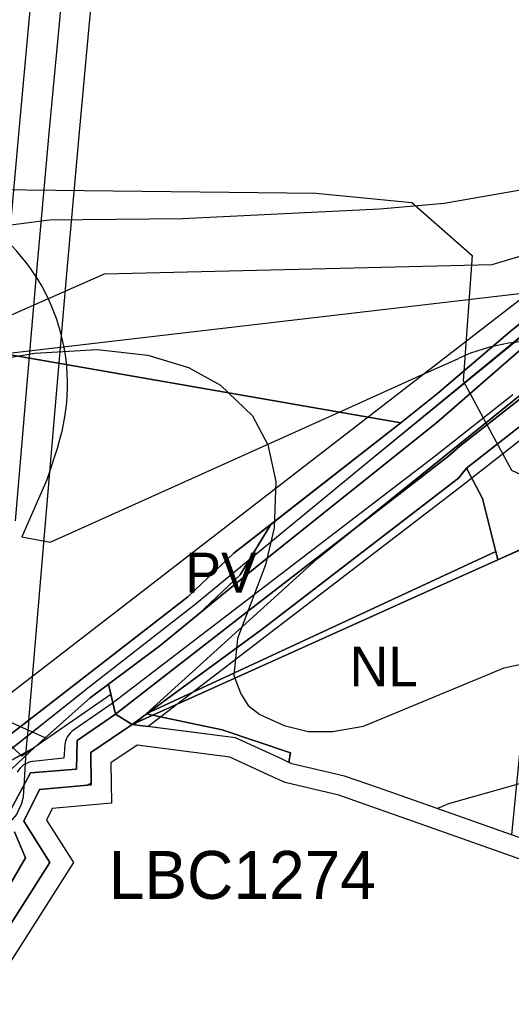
# Model space of a CAD drawing. Extents: x -758499 to -754160, y -1175205 to -1172032.
# Drawn here: x -756598.2 to -756475, y -1174594.7 to -1174350.7 of the extents above; entities that cross this region are included whole.
import ezdxf

# ---------------------------------------------------------------- set-up
doc = ezdxf.new("R2010")
doc.units = 0
for name, color, linetype in [('A040_Les50_p', 7, 'Continuous'), ('A041_BPEJ_p', 7, 'Continuous'), ('A043_InvPuda_p', 7, 'Continuous'), ('A050_Q100_p', 7, 'Continuous'), ('A053_ZvlPovoden_p', 7, 'Continuous'), ('A068_Vodovod_l', 7, 'Continuous'), ('A082_RSS_l', 7, 'Continuous'), ('A106_CykloT_l', 7, 'Continuous'), ('A106_TuristT_l', 7, 'Continuous'), ('HRANICE změn v krajině', 7, 'Continuous'), ('HRANICE řešeného území', 7, 'Continuous'), ('indexy RZV_TYP_1', 7, 'Continuous'), ('LIMITY OP vodovodu', 7, 'Continuous'), ('NÁVRH NL lesní', 7, 'Continuous'), ('PLOCHY NL lesní', 7, 'Continuous'), ('PLOCHY NS smíšené nezastavěného území', 7, 'Continuous'), ('PLOCHY NZo zemědělské-orná půda', 7, 'Continuous'), ('PLOCHY NZt zeměděl-trvalý travní porost', 7, 'Continuous'), ('PLOCHY PV prostranství veřejné', 7, 'Continuous'), ('PLOCHY VV vodní a vodohospodářské', 7, 'Continuous'), ('protipovodňová opatření- obnova ramene NÁVRH', 7, 'Continuous'), ('VPO RO retenční opatření - plochy', 7, 'Continuous'), ('vrstevnice', 7, 'Continuous'), ('ZPF obrys ploch k odnětí', 7, 'Continuous'), ('ZPF třída ochrany III', 7, 'Continuous'), ('ÚSES LBC jako součást RBK', 7, 'Continuous'), ('ÚSES LBK funkční', 7, 'Continuous'), ('ÚSES NBK funkční', 7, 'Continuous')]:
    doc.layers.add(name, color=color, linetype=linetype)

msp = doc.modelspace()

# ---------------------------------------------------------------- linework, layer by layer
at = {"layer": 'A040_Les50_p'}
for p, q in [((-756498.95, -1174440.27), (-756488.31, -1174435.48)), ((-756515.76, -1174447.84), (-756498.95, -1174440.27))]:
    msp.add_line(p, q, dxfattribs=at)
for points in [[(-756590.49, -1174481.49), (-756585.1, -1174479.07), (-756515.76, -1174447.84)], [(-756588.52, -1174457.25), (-756591.29, -1174465.89), (-756597.6, -1174480.1), (-756590.49, -1174481.49)]]:
    msp.add_lwpolyline(points, dxfattribs=at)
for centre, start, end in [((-756636.13, -1174441.98), 342.2144, 114.2004), ((-756467.78, -1174481.07), 354.3867, 114.2367), ((-756478.42, -1174485.86), 114.2367, 114.2433), ((-756495.23, -1174493.43), 114.2433, 114.247)]:
    msp.add_arc(centre, 50, start, end, dxfattribs=at)
at = {"layer": 'A041_BPEJ_p'}
for p, q in [((-756437.63, -1174416.24), (-756515.58, -1174479.13)), ((-756515.58, -1174479.13), (-756437.63, -1174416.24)), ((-756475.43, -1174428.83), (-756458.44, -1174415.07)), ((-756458.44, -1174415.07), (-756475.43, -1174428.83)), ((-756493.49, -1174444.31), (-756475.43, -1174428.83)), ((-756475.43, -1174428.83), (-756493.49, -1174444.31)), ((-756471.9, -1174432.58), (-756493.78, -1174451.61)), ((-756493.78, -1174451.61), (-756471.9, -1174432.58)), ((-756502.69, -1174451.65), (-756493.49, -1174444.31)), ((-756493.49, -1174444.31), (-756502.69, -1174451.65)), ((-756493.78, -1174451.61), (-756538.25, -1174487.18)), ((-756538.25, -1174487.18), (-756493.78, -1174451.61)), ((-756535.23, -1174477.02), (-756502.69, -1174451.65)), ((-756502.69, -1174451.65), (-756535.23, -1174477.02)), ((-756542.94, -1174489.61), (-756535.23, -1174477.02)), ((-756535.23, -1174477.02), (-756542.94, -1174489.61)), ((-756515.58, -1174479.13), (-756541.52, -1174499.18)), ((-756523.67, -1174485.65), (-756515.58, -1174479.13)), ((-756467.78, -1174481.07), (-756478.42, -1174485.86)), ((-756478.42, -1174485.86), (-756467.78, -1174481.07)), ((-756478.94, -1174483.82), (-756566.43, -1174524.45)), ((-756566.43, -1174524.45), (-756478.94, -1174483.82)), ((-756478.42, -1174485.86), (-756478.94, -1174483.82)), ((-756478.94, -1174483.82), (-756478.42, -1174485.86)), ((-756566.43, -1174524.45), (-756523.67, -1174485.65)), ((-756538.25, -1174487.18), (-756553.39, -1174499.51)), ((-756553.39, -1174499.51), (-756538.25, -1174487.18)), ((-756553.39, -1174499.51), (-756542.94, -1174489.61)), ((-756542.94, -1174489.61), (-756553.39, -1174499.51)), ((-756541.52, -1174499.18), (-756569.68, -1174521.07)), ((-756575.27, -1174519.59), (-756597.58, -1174535.01)), ((-756574.1, -1174524.5), (-756575.27, -1174519.59)), ((-756569.68, -1174521.07), (-756574.1, -1174524.5)), ((-756569.49, -1174527.16), (-756566.43, -1174524.45)), ((-756547.43, -1174528.41), (-756566.43, -1174524.45)), ((-756566.43, -1174524.45), (-756547.43, -1174528.41)), ((-756530.34, -1174534.21), (-756547.43, -1174528.41)), ((-756547.43, -1174528.41), (-756530.34, -1174534.21)), ((-756597.58, -1174535.01), (-756602.01, -1174530.76)), ((-756530.73, -1174536.56), (-756530.34, -1174534.21)), ((-756530.34, -1174534.21), (-756530.73, -1174536.56)), ((-756581.6, -1174542.33), (-756580.21, -1174541.74))]:
    msp.add_line(p, q, dxfattribs=at)
for points in [[(-756530.73, -1174536.56), (-756531.23, -1174536.33), (-756532.74, -1174535.64), (-756544.1, -1174530.4), (-756569.49, -1174527.16)], [(-756475, -1174554.72), (-756497.9, -1174546.65), (-756508.56, -1174542.9), (-756516.8, -1174540), (-756530, -1174536.9), (-756530.73, -1174536.56)], [(-756580.21, -1174541.74), (-756580.2, -1174542.2), (-756581.6, -1174542.33)]]:
    msp.add_lwpolyline(points, dxfattribs=at)
at = {"layer": 'A043_InvPuda_p'}
msp.add_line((-756366.82, -1174338.86), (-756610.15, -1174526.83), dxfattribs=at)
at = {"layer": 'A050_Q100_p'}
for p, q in [((-756640.05, -1174392.82), (-756523.95, -1174394.14)), ((-756523.95, -1174394.14), (-756499.99, -1174396.5)), ((-756499.99, -1174396.5), (-756484.85, -1174409.74)), ((-756484.85, -1174409.74), (-756487.12, -1174441.13)), ((-756487.12, -1174441.13), (-756475.01, -1174463.45)), ((-756475.01, -1174463.45), (-756453.44, -1174473.66))]:
    msp.add_line(p, q, dxfattribs=at)
at = {"layer": 'A053_ZvlPovoden_p'}
msp.add_lwpolyline([(-756442.75, -1174566.23), (-756447.2, -1174564.5), (-756475, -1174554.72), (-756497.9, -1174546.65), (-756508.56, -1174542.9), (-756516.8, -1174540), (-756530, -1174536.9), (-756531.23, -1174536.33), (-756532.74, -1174535.64), (-756544.1, -1174530.4), (-756570, -1174527.1), (-756580.3, -1174534.1), (-756580.2, -1174542.2), (-756593.2, -1174543.4), (-756597.1, -1174551.3), (-756590.6, -1174561.6), (-756610.6, -1174593)], dxfattribs=at)
at = {"layer": 'A068_Vodovod_l'}
for p, q in [((-756585.96, -1174328.29), (-756588.26, -1174351.74)), ((-756588.26, -1174351.74), (-756590.71, -1174378.21)), ((-756590.71, -1174378.21), (-756593.98, -1174414.56)), ((-756593.98, -1174414.56), (-756596.79, -1174447.61)), ((-756596.79, -1174447.61), (-756599.23, -1174476.12))]:
    msp.add_line(p, q, dxfattribs=at)
at = {"layer": 'A082_RSS_l'}
msp.add_line((-755336.54, -1174286.94), (-757157.2, -1174499.04), dxfattribs=at)
at = {"layer": 'A106_CykloT_l'}
for p, q in [((-756454.78, -1174415.63), (-756510.66, -1174461.22)), ((-756510.66, -1174461.22), (-756554.2, -1174497.04)), ((-756554.2, -1174497.04), (-756580.75, -1174517.73))]:
    msp.add_line(p, q, dxfattribs=at)
msp.add_lwpolyline([(-756580.75, -1174517.73), (-756603.81, -1174536.06), (-756634.48, -1174569.59), (-756661.16, -1174595.4)], dxfattribs=at)
at = {"layer": 'A106_TuristT_l'}
for p, q in [((-756428.85, -1174393.94), (-756510.66, -1174461.22)), ((-756510.66, -1174461.22), (-756554.2, -1174497.04)), ((-756554.2, -1174497.04), (-756580.75, -1174517.73)), ((-756580.75, -1174517.73), (-756603.81, -1174536.06))]:
    msp.add_line(p, q, dxfattribs=at)
msp.add_lwpolyline([(-756901.81, -1174477.78), (-756825.76, -1174458.08), (-756805.07, -1174450.48), (-756774.77, -1174444.62), (-756739.5, -1174452.1), (-756705.96, -1174463.81), (-756685.13, -1174462.93), (-756614.4, -1174430.84), (-756576.87, -1174414.32), (-756479.81, -1174411.97), (-756441.96, -1174400.66), (-756428.85, -1174393.94), (-756406.85, -1174376.99), (-756377.92, -1174355.05), (-756340.65, -1174330.24), (-756331.67, -1174321.14), (-756326.19, -1174313.66), (-756309.92, -1174288.16), (-756301.82, -1174281.12), (-756289.96, -1174275.89), (-756280.72, -1174271.65), (-756256.13, -1174262.02)], dxfattribs=at)
at = {"layer": 'HRANICE změn v krajině'}
msp.add_lwpolyline([(-756613.9, -1174432.27), (-756502.69, -1174451.65), (-756544.5, -1174484.25), (-756556, -1174495.16), (-756604.81, -1174532.93), (-756607.52, -1174529.11), (-756625.33, -1174530.37), (-756641.8, -1174531.53), (-756666.1, -1174529.35), (-756673.17, -1174508.23), (-756675.5, -1174493.21), (-756673.73, -1174478.91), (-756666.63, -1174470), (-756639.71, -1174453.14), (-756636.13, -1174441.98)], close=True, dxfattribs=at)
at = {"layer": 'HRANICE řešeného území'}
for points in [[(-756475, -1174554.72), (-756497.9, -1174546.65), (-756508.56, -1174542.9), (-756516.8, -1174540), (-756530, -1174536.9), (-756531.23, -1174536.33), (-756532.74, -1174535.64), (-756544.1, -1174530.4), (-756570, -1174527.1), (-756580.3, -1174534.1), (-756580.2, -1174542.2), (-756593.2, -1174543.4), (-756597.1, -1174551.3), (-756590.6, -1174561.6), (-756610.6, -1174593)], [(-756367.06, -1174596.6), (-756372.97, -1174591.62), (-756376.82, -1174591), (-756404.32, -1174586.55), (-756448.94, -1174569.19), (-756476.66, -1174559.44), (-756499.56, -1174551.37), (-756510.22, -1174547.62), (-756518.21, -1174544.81), (-756531.64, -1174541.65), (-756533.32, -1174540.87), (-756534.83, -1174540.18), (-756545.5, -1174535.26), (-756568.75, -1174532.3), (-756575.27, -1174536.73), (-756575.14, -1174546.75), (-756589.95, -1174548.12), (-756591.38, -1174551), (-756584.68, -1174561.61), (-756607.86, -1174598)]]:
    msp.add_lwpolyline(points, dxfattribs=at)
at = {"layer": 'LIMITY OP vodovodu'}
for points in [[(-756612.1, -1174541.9), (-756611.43, -1174531.5), (-756610.91, -1174526.01), (-756610.88, -1174525.27), (-756609.05, -1174503.19), (-756606.7, -1174475.48), (-756604.26, -1174446.97), (-756601.45, -1174413.91), (-756598.18, -1174377.53), (-756595.73, -1174351.03), (-756593.43, -1174327.57), (-756590.26, -1174293.95), (-756587.21, -1174262.59), (-756583.86, -1174228.7), (-756581.33, -1174202.7), (-756579.89, -1174188.54), (-756578.84, -1174178.02), (-756578.54, -1174175.16), (-756577.64, -1174172.89), (-756577.05, -1174171.67), (-756575.76, -1174169.64), (-756574.67, -1174167.87), (-756569.8, -1174160.13)], [(-756557.1, -1174168.11), (-756561.93, -1174175.79), (-756563.04, -1174177.6), (-756563.85, -1174178.86), (-756563.92, -1174179.54), (-756564.97, -1174190.04), (-756566.41, -1174204.18), (-756568.94, -1174230.16), (-756572.29, -1174264.05), (-756575.32, -1174295.37), (-756578.49, -1174329.01), (-756580.79, -1174352.45), (-756583.24, -1174378.89), (-756586.51, -1174415.21), (-756589.32, -1174448.25), (-756591.76, -1174476.76), (-756594.11, -1174504.45), (-756595.9, -1174526.17), (-756595.93, -1174527.01), (-756596.47, -1174532.7), (-756597.29, -1174545.26), (-756597.77, -1174547.1), (-756598.93, -1174549.6), (-756600.54, -1174551.47)]]:
    msp.add_lwpolyline(points, dxfattribs=at)
at = {"layer": 'NÁVRH NL lesní'}
msp.add_lwpolyline([(-756613.9, -1174432.27), (-756502.69, -1174451.65), (-756544.5, -1174484.25), (-756556, -1174495.16), (-756604.81, -1174532.93), (-756607.52, -1174529.11), (-756625.33, -1174530.37), (-756641.8, -1174531.53), (-756666.1, -1174529.35), (-756673.17, -1174508.23), (-756675.5, -1174493.21), (-756673.73, -1174478.91), (-756666.63, -1174470), (-756639.71, -1174453.14), (-756636.13, -1174441.98)], close=True, dxfattribs=at)
at = {"layer": 'PLOCHY NL lesní'}
for points in [[(-756570, -1174527.1), (-756564.59, -1174524.67), (-756495.23, -1174493.43), (-756478.42, -1174485.86), (-756467.78, -1174481.07), (-756468.64, -1174489.82), (-756469.2, -1174495.51), (-756475, -1174554.72)], [(-756601.31, -1174536.7), (-756594.43, -1174532.87), (-756582.65, -1174522.32), (-756580.51, -1174520.41), (-756575.9, -1174516.97), (-756574.1, -1174524.5)], [(-756574.1, -1174524.5), (-756583.7, -1174531.1), (-756583.9, -1174538.25), (-756595.4, -1174539.2), (-756601.1, -1174549.8)], [(-756475, -1174554.72), (-756497.9, -1174546.65), (-756508.56, -1174542.9), (-756516.8, -1174540), (-756530, -1174536.9), (-756531.23, -1174536.33), (-756532.74, -1174535.64), (-756544.1, -1174530.4), (-756570, -1174527.1)], [(-756599.39, -1174553.97), (-756596.7, -1174560.5), (-756612.7, -1174588)]]:
    msp.add_lwpolyline(points, dxfattribs=at)
at = {"layer": 'PLOCHY NS smíšené nezastavěného území'}
for points in [[(-756575.9, -1174516.97), (-756563.06, -1174507.38), (-756538.25, -1174487.18), (-756493.78, -1174451.61), (-756471.9, -1174432.58), (-756418.03, -1174389.24), (-756373.32, -1174354.68), (-756338.47, -1174332.88), (-756334.96, -1174337.03), (-756352.64, -1174351.01), (-756353.14, -1174350.92), (-756359.86, -1174354.49), (-756374.36, -1174365.88), (-756377.15, -1174370.5), (-756415.51, -1174400.7), (-756487.92, -1174457.46), (-756490.69, -1174459.88), (-756541.52, -1174499.18), (-756574.1, -1174524.5)], [(-756486.27, -1174462.92), (-756482.28, -1174470.54), (-756478.42, -1174485.86), (-756495.23, -1174493.43), (-756564.59, -1174524.67), (-756570, -1174527.1), (-756537.41, -1174503.22), (-756488.31, -1174465.49)]]:
    msp.add_lwpolyline(points, close=True, dxfattribs=at)
at = {"layer": 'PLOCHY NZo zemědělské-orná půda'}
msp.add_lwpolyline([(-756484.77, -1174220.66), (-756461.31, -1174236.59), (-756405.36, -1174274.59), (-756360.45, -1174308.59), (-756343.13, -1174327.37), (-756379.08, -1174352.38), (-756421.32, -1174383.97), (-756458.44, -1174415.07), (-756475.43, -1174428.83), (-756493.49, -1174444.31), (-756502.69, -1174451.65), (-756613.9, -1174432.27)], dxfattribs=at)
at = {"layer": 'PLOCHY NZt zeměděl-trvalý travní porost'}
msp.add_lwpolyline([(-756467.78, -1174481.07), (-756478.42, -1174485.86), (-756482.28, -1174470.54), (-756486.27, -1174462.92), (-756416.94, -1174408.7)], dxfattribs=at)
at = {"layer": 'PLOCHY PV prostranství veřejné'}
msp.add_lwpolyline([(-756604.81, -1174532.93), (-756556, -1174495.16), (-756544.5, -1174484.25), (-756502.69, -1174451.65), (-756493.49, -1174444.31), (-756475.43, -1174428.83), (-756458.44, -1174415.07), (-756421.32, -1174383.97), (-756379.08, -1174352.38), (-756343.13, -1174327.37), (-756338.47, -1174332.88), (-756373.32, -1174354.68), (-756418.03, -1174389.24), (-756471.9, -1174432.58), (-756493.78, -1174451.61), (-756538.25, -1174487.18), (-756563.06, -1174507.38), (-756575.9, -1174516.97), (-756580.51, -1174520.41), (-756582.65, -1174522.32), (-756594.43, -1174532.87), (-756601.31, -1174536.7)], dxfattribs=at)
at = {"layer": 'PLOCHY VV vodní a vodohospodářské'}
for points in [[(-756601.1, -1174549.8), (-756595.4, -1174539.2), (-756583.9, -1174538.25), (-756583.7, -1174531.1), (-756574.1, -1174524.5), (-756541.52, -1174499.18), (-756490.69, -1174459.88), (-756487.92, -1174457.46), (-756415.51, -1174400.7), (-756377.15, -1174370.5), (-756373.42, -1174375.25), (-756416.94, -1174408.7), (-756486.27, -1174462.92), (-756488.31, -1174465.49), (-756537.41, -1174503.22), (-756570, -1174527.1), (-756580.3, -1174534.1), (-756580.2, -1174542.2), (-756593.2, -1174543.4), (-756597.1, -1174551.3), (-756590.6, -1174561.6), (-756610.6, -1174593)], [(-756612.7, -1174588), (-756596.7, -1174560.5), (-756599.39, -1174553.97)]]:
    msp.add_lwpolyline(points, dxfattribs=at)
at = {"layer": 'protipovodňová opatření- obnova ramene NÁVRH'}
for points in [[(-756474.64, -1174444.6), (-756494.12, -1174459.92), (-756574.96, -1174521.85), (-756584.64, -1174528.51)], [(-756570, -1174527.1), (-756566.04, -1174527.61), (-756487.98, -1174467.82), (-756471.15, -1174454.58)], [(-756761.49, -1174675.51), (-756758.45, -1174677.3), (-756755.6, -1174680.3), (-756739, -1174682.9), (-756740, -1174669.4), (-756730.8, -1174654.1), (-756715.6, -1174644.8), (-756707.5, -1174656), (-756668, -1174629.7), (-756658.1, -1174631.4), (-756657.1, -1174613.9), (-756646, -1174616.1), (-756639, -1174610.2), (-756631.1, -1174626.8), (-756615.6, -1174617), (-756622.6, -1174593), (-756610.6, -1174593), (-756590.6, -1174561.6), (-756597.1, -1174551.3), (-756593.2, -1174543.4), (-756580.2, -1174542.2), (-756580.3, -1174534.1), (-756570, -1174527.1)], [(-756586.78, -1174532.19), (-756587.07, -1174535.49), (-756594.87, -1174536.37)]]:
    msp.add_lwpolyline(points, dxfattribs=at)
for centre, start, end in [((-756581.8, -1174532.62), 124.5369, 175.0282), ((-756594.31, -1174541.34), 96.4655, 152.2904)]:
    msp.add_arc(centre, 5, start, end, dxfattribs=at)
at = {"layer": 'VPO RO retenční opatření - plochy'}
for points in [[(-756474.64, -1174444.6), (-756494.12, -1174459.92), (-756574.96, -1174521.85), (-756584.64, -1174528.51)], [(-756570, -1174527.1), (-756566.04, -1174527.61), (-756487.98, -1174467.82), (-756471.15, -1174454.58)], [(-756761.49, -1174675.51), (-756758.45, -1174677.3), (-756755.6, -1174680.3), (-756739, -1174682.9), (-756740, -1174669.4), (-756730.8, -1174654.1), (-756715.6, -1174644.8), (-756707.5, -1174656), (-756668, -1174629.7), (-756658.1, -1174631.4), (-756657.1, -1174613.9), (-756646, -1174616.1), (-756639, -1174610.2), (-756631.1, -1174626.8), (-756615.6, -1174617), (-756622.6, -1174593), (-756610.6, -1174593), (-756590.6, -1174561.6), (-756597.1, -1174551.3), (-756593.2, -1174543.4), (-756580.2, -1174542.2), (-756580.3, -1174534.1), (-756570, -1174527.1)], [(-756586.78, -1174532.19), (-756587.07, -1174535.49), (-756594.87, -1174536.37)]]:
    msp.add_lwpolyline(points, dxfattribs=at)
for centre, start, end in [((-756581.8, -1174532.62), 124.5369, 175.0282), ((-756594.31, -1174541.34), 96.4655, 152.2904)]:
    msp.add_arc(centre, 5, start, end, dxfattribs=at)
at = {"layer": 'vrstevnice'}
for p, q in [((-756491.82, -1174396.62), (-756470.32, -1174392.87)), ((-756507.99, -1174398.06), (-756491.82, -1174396.62)), ((-756557.35, -1174400.51), (-756507.99, -1174398.06)), ((-756608.72, -1174403.11), (-756590.68, -1174400.8)), ((-756590.68, -1174400.8), (-756557.35, -1174400.51)), ((-756625.47, -1174439.63), (-756594.29, -1174434.14)), ((-756625.47, -1174439.63), (-756594.29, -1174434.14)), ((-756594.29, -1174434.14), (-756578.71, -1174433.28)), ((-756594.29, -1174434.14), (-756578.71, -1174433.28)), ((-756578.71, -1174433.28), (-756566, -1174434.72)), ((-756578.71, -1174433.28), (-756566, -1174434.72)), ((-756566, -1174434.72), (-756555.9, -1174437.75)), ((-756566, -1174434.72), (-756555.9, -1174437.75)), ((-756555.9, -1174437.75), (-756547.82, -1174442.22)), ((-756555.9, -1174437.75), (-756547.82, -1174442.22)), ((-756547.82, -1174442.22), (-756539.88, -1174449.87)), ((-756547.82, -1174442.22), (-756539.88, -1174449.87)), ((-756539.88, -1174449.87), (-756535.99, -1174457.09)), ((-756539.88, -1174449.87), (-756535.99, -1174457.09)), ((-756535.99, -1174457.09), (-756533.96, -1174466.33)), ((-756535.99, -1174457.09), (-756533.96, -1174466.33)), ((-756533.96, -1174466.33), (-756534.4, -1174477.87)), ((-756533.96, -1174466.33), (-756534.4, -1174477.87)), ((-756534.4, -1174477.87), (-756536.56, -1174487.11)), ((-756534.4, -1174477.87), (-756536.56, -1174487.11)), ((-756536.56, -1174487.11), (-756543.63, -1174505.58)), ((-756536.56, -1174487.11), (-756543.63, -1174505.58)), ((-756543.63, -1174505.58), (-756544.5, -1174514.82)), ((-756543.63, -1174505.58), (-756544.5, -1174514.82)), ((-756476.81, -1174512.94), (-756463.82, -1174510.06)), ((-756476.81, -1174512.94), (-756463.82, -1174510.06)), ((-756512.03, -1174527.52), (-756476.81, -1174512.94)), ((-756512.03, -1174527.52), (-756476.81, -1174512.94)), ((-756544.5, -1174514.82), (-756542.77, -1174519.44)), ((-756544.5, -1174514.82), (-756542.77, -1174519.44)), ((-756542.77, -1174519.44), (-756540.89, -1174522.32)), ((-756542.77, -1174519.44), (-756540.89, -1174522.32)), ((-756540.89, -1174522.32), (-756538.01, -1174524.63)), ((-756540.89, -1174522.32), (-756538.01, -1174524.63)), ((-756538.01, -1174524.63), (-756531.94, -1174527.37)), ((-756538.01, -1174524.63), (-756531.94, -1174527.37)), ((-756531.94, -1174527.37), (-756525.88, -1174528.82)), ((-756531.94, -1174527.37), (-756525.88, -1174528.82)), ((-756525.88, -1174528.82), (-756519.82, -1174528.82)), ((-756525.88, -1174528.82), (-756519.82, -1174528.82)), ((-756519.82, -1174528.82), (-756512.03, -1174527.52)), ((-756519.82, -1174528.82), (-756512.03, -1174527.52)), ((-756490.67, -1174546.86), (-756467.29, -1174540.22)), ((-756490.67, -1174546.86), (-756467.29, -1174540.22)), ((-756493.65, -1174548.15), (-756490.67, -1174546.86)), ((-756493.65, -1174548.15), (-756490.67, -1174546.86))]:
    msp.add_line(p, q, dxfattribs=at)
at = {"layer": 'ZPF obrys ploch k odnětí'}
msp.add_lwpolyline([(-756613.9, -1174432.27), (-756502.69, -1174451.65), (-756544.5, -1174484.25), (-756556, -1174495.16), (-756604.81, -1174532.93), (-756607.52, -1174529.11), (-756625.33, -1174530.37), (-756641.8, -1174531.53), (-756666.1, -1174529.35), (-756673.17, -1174508.23), (-756675.5, -1174493.21), (-756673.73, -1174478.91), (-756666.63, -1174470), (-756639.71, -1174453.14), (-756636.13, -1174441.98)], close=True, dxfattribs=at)
at = {"layer": 'ZPF třída ochrany III'}
msp.add_lwpolyline([(-756638.7, -1174450), (-756639.71, -1174453.14), (-756653.39, -1174461.71), (-756666.63, -1174470), (-756673.73, -1174478.91), (-756675.5, -1174493.21), (-756673.17, -1174508.23), (-756666.1, -1174529.35), (-756641.8, -1174531.53), (-756625.33, -1174530.37), (-756619.86, -1174529.98), (-756619.57, -1174529.99), (-756619.22, -1174529.96), (-756607.47, -1174529.18), (-756604.81, -1174532.93), (-756602.01, -1174530.76), (-756556, -1174495.16), (-756544.5, -1174484.25), (-756535.23, -1174477.03), (-756535.23, -1174477.02), (-756502.69, -1174451.65), (-756613.9, -1174432.27), (-756636.13, -1174441.98), (-756638.7, -1174450)], dxfattribs=at)
at = {"layer": 'ÚSES LBC jako součást RBK'}
for p, q in [((-756486.27, -1174462.92), (-756488.31, -1174465.49)), ((-756482.28, -1174470.54), (-756486.27, -1174462.92)), ((-756488.31, -1174465.49), (-756537.41, -1174503.22)), ((-756478.42, -1174485.86), (-756482.28, -1174470.54)), ((-756467.7, -1174481.09), (-756478.42, -1174485.86)), ((-756537.41, -1174503.22), (-756570, -1174527.1)), ((-756575.9, -1174516.97), (-756580.51, -1174520.41)), ((-756574.1, -1174524.5), (-756575.9, -1174516.97)), ((-756580.51, -1174520.41), (-756591.73, -1174530.46)), ((-756570, -1174527.1), (-756574.1, -1174524.5)), ((-756591.73, -1174530.46), (-756594.43, -1174532.87)), ((-756594.43, -1174532.87), (-756599.99, -1174538.12))]:
    msp.add_line(p, q, dxfattribs=at)
at = {"layer": 'ÚSES LBK funkční'}
for p, q in [((-756471.9, -1174432.58), (-756493.78, -1174451.61)), ((-756493.78, -1174451.61), (-756538.25, -1174487.18)), ((-756488.31, -1174465.49), (-756486.27, -1174462.92)), ((-756486.27, -1174462.92), (-756482.28, -1174470.54)), ((-756537.41, -1174503.22), (-756488.31, -1174465.49)), ((-756482.28, -1174470.54), (-756478.42, -1174485.86)), ((-756478.42, -1174485.86), (-756467.7, -1174481.09)), ((-756538.25, -1174487.18), (-756563.06, -1174507.38)), ((-756570, -1174527.1), (-756537.41, -1174503.22)), ((-756563.06, -1174507.38), (-756575.9, -1174516.97)), ((-756575.9, -1174516.97), (-756574.1, -1174524.5)), ((-756574.1, -1174524.5), (-756570, -1174527.1))]:
    msp.add_line(p, q, dxfattribs=at)
at = {"layer": 'ÚSES NBK funkční'}
msp.add_line((-756591.73, -1174530.46), (-756675.5, -1174493.24), dxfattribs=at)

# ---------------------------------------------------------------- texts
at = {"layer": 'indexy RZV_TYP_1'}
for s, p in [('PV', (-756556.63, -1174494.11)), ('NL', (-756515.52, -1174517.58))]:
    msp.add_text(s, height=10, dxfattribs=at).set_placement(p)
at = {"layer": 'ÚSES LBC jako součást RBK'}
msp.add_text('LBC1274', height=12, dxfattribs=at).set_placement((-756575.85, -1174570.74))

doc.saveas('drawing.dxf')
